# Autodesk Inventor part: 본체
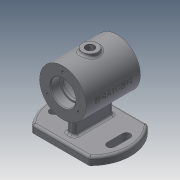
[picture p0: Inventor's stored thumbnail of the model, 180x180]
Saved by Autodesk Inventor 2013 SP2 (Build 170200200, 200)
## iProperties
Created: 2021-09
Part Number: 본체
Material: Generic
Document SubType Name: Modeling
Designer: kumcom13
Density: 1 g/cm^3
Mass: 173.306 g
Surface Area: 487.025 cm^2
Volume: 173.306 cm^3
Author: kumcom13
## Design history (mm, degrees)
sketch "스케치1"
  geometry: L1 (0, 35)-(0, -35); L2 (0, 35)-(16, 35); L3 (30, 35)-(30, -35); L4 (30, -35)-(16, -35); L5 (16, 35)-(16, 23.3); L6 (15.7, 23)-(14, 23); L7 (14, 23)-(14, 20); L8 (14, 20)-(22, 20); L9 (25, 17)-(25, -17); L10 (22, -20)-(14, -20); L11 (14, -20)-(14, -23); L12 (14, -23)-(15.7, -23); L13 (16, -23.3)-(16, -35); L14 (16, 35)-(30, 35); L15 (16, -35)-(0, -35); A1 r 0.3 centre (15.7, 23.3) between (15.7, 23) and (16, 23.3); A2 r 0.3 centre (15.7, -23.3) between (16, -23.3) and (15.7, -23); A3 r 3 centre (22, 17) between (25, 17) and (22, 20); A4 r 3 centre (22, -17) between (22, -20) and (25, -17); 4 further points
  constraints: 30 end point, 16 perpendicular, 8 parallel, 8 point on circle, 8 tangent, 4 centre point, 4 point on line, 2 collinear, 1 coincident, 1 equal radius, 1 midpoint, 1 vertical
  dimensions: "d0" = 70 distance of L1.start L1.end; "d2" = 60 diameter of L3 L1; "d3" = 32 diameter of L5 L1; "d4" = 28 diameter of L7 L1; "d5" = 50 diameter of L9 L1; "d7" = 12 distance between parallel lines of L6 L2; "d8" = 40 distance between parallel lines of L8 L10; "d9" = 12 distance between parallel lines of L4 L12; "d10" = 3 distance between parallel lines of L8 L6; "d11" = 0.3 radius of A1; "d12" = 0.3 radius of A2; "d14" = 3 radius of A3
revolve "회전1" sketch "스케치1" stored, may be unused: angle "d13" = 90 deg
chamfer "모따기1" distance "d15" = 1; stored, may be unused: second distance "d16" = 3.175, angle "d17" = 45 deg
node "작업 평면1"
sketch "스케치2"
  geometry: L1 (-36.742, -37.5)-(36.742, -37.5); L2 (36.742, 37.5)-(-36.742, 37.5); L3 (-32, -10)-(-42, -10); L4 (-42, -10)-(-42, 10); L5 (-42, 10)-(-32, 10); L6 (-32, 10)-(-32, -10); L7 (-32, -10)-(-42, 10); L8 (-42, -10)-(-32, 10); L9 (0, 0)-(0, 27.216); L10 (32, -10)-(42, -10); L11 (42, -10)-(42, 10); L12 (42, 10)-(32, 10); L13 (32, 10)-(32, -10); L14 (32, -10)-(42, 10); L15 (42, -10)-(32, 10); A1 r 52.5 centre (0, 0) between (36.742, -37.5) and (36.742, 37.5); A2 r 52.5 centre (0, 0) between (-36.742, 37.5) and (-36.742, -37.5); A3 r 5 centre (-37, -10) between (-42, -10) and (-32, -10); A4 r 5 centre (-37, 10) between (-32, 10) and (-42, 10); A5 r 5 centre (37, -10) between (32, -10) and (42, -10); A6 r 5 centre (37, 10) between (42, 10) and (32, 10); 4 further points
  constraints: 30 end point, 12 point on circle, 8 midpoint, 6 centre point, 5 symmetric about line, 4 parallel, 2 horizontal, 1 coincident, 1 horizontal alignment, 1 perpendicular
  dimensions: "d21" = 75 distance between parallel lines of L2 L1; "d22" = 37.5 distance from line of point (0, 0) L1; "d23" = 52.5 radius of A2; "d24" = 52.5 radius of A1; "d25" = 10 distance of L4.end L5.end; "d26" = 20 distance of L4.end L3.end; "d27" = 10 distance from line of point (0, 0) L3; "d28" = 37 distance of point (0, 0) point (-37, 0)
extrude "돌출1" join sketch "스케치2" distance "d29" = 10; taper "d30" = 0 deg
sketch "스케치3"
  geometry: L1 (5, 25)-(-5, 25); L2 (-5, 25)-(-5, -25); L3 (-5, -25)-(5, -25); L4 (5, -25)-(5, 25); L5 (5, 25)-(-5, -25); L6 (-5, 25)-(5, -25); A1 r 52.5 centre (0, 0) between (-36.742, 37.5) and (-36.742, -37.5) reference
  constraints: 12 end point, 2 midpoint, 2 parallel, 1 horizontal, 1 perpendicular
  dimensions: "d31" = 10 distance of L3.end L2.end; "d32" = 50 distance of L2.end L1.end
extrude "돌출2" join sketch "스케치3" stored distance "d33" = 10; taper "d34" = 0 deg
fillet "모깎기1" dims "d35" = 3
fillet "모깎기2" dims "d36" = 3
node "작업 평면2"
sketch "스케치4"
  geometry: C1 r 10 at (0, 0); 1 further point
  constraints: 1 centre point, 1 coincident
  dimensions: "d38" = 20 diameter of C1
extrude "돌출3" join sketch "스케치4" stored distance "d40" = 10; taper "d41" = 0 deg
hole "구멍1" diameter "d44" = 10.922; stored, may be unused: countersink angle "d48" = 82 deg, drill point angle "d50" = 118 deg; dims "d42" = 25.4, "d43" = 25.4, "d45" = 19.05, "d46" = 9.525, "d47" = 6.35, "d49" = 25.4
sketch "스케치5"
  geometry: C1 r 30 at (0, 0) reference; 1 further point
  constraints: 1 vertical alignment
  dimensions: "d51" = 23 distance of C1.centre point (0, 23)
hole "구멍2" sketch "스케치5" at (0, 23) diameter "d52" = 3.2512; stored, may be unused: countersink angle "d56" = 82 deg, drill point angle "d58" = 118 deg; dims "d53" = 8, "d54" = 9.525, "d55" = 6.35, "d57" = 10
fillet "모깎기3" dims "d62" = 3
node "작업 평면3"
sketch "스케치6"
  geometry: 2 further points
  constraints: 1 coincident, 1 other
feature "엠보싱1" sketch "스케치6" dims "d2" = 60, "d64" = 0.5, "d65" = 0
node "솔리드1"
pattern_circular "원형 패턴1" dims angle "d60" = 360 deg
mirror "대칭1"
other parameters: "d18" = -62, "d19" = 105, "d37" = 33
